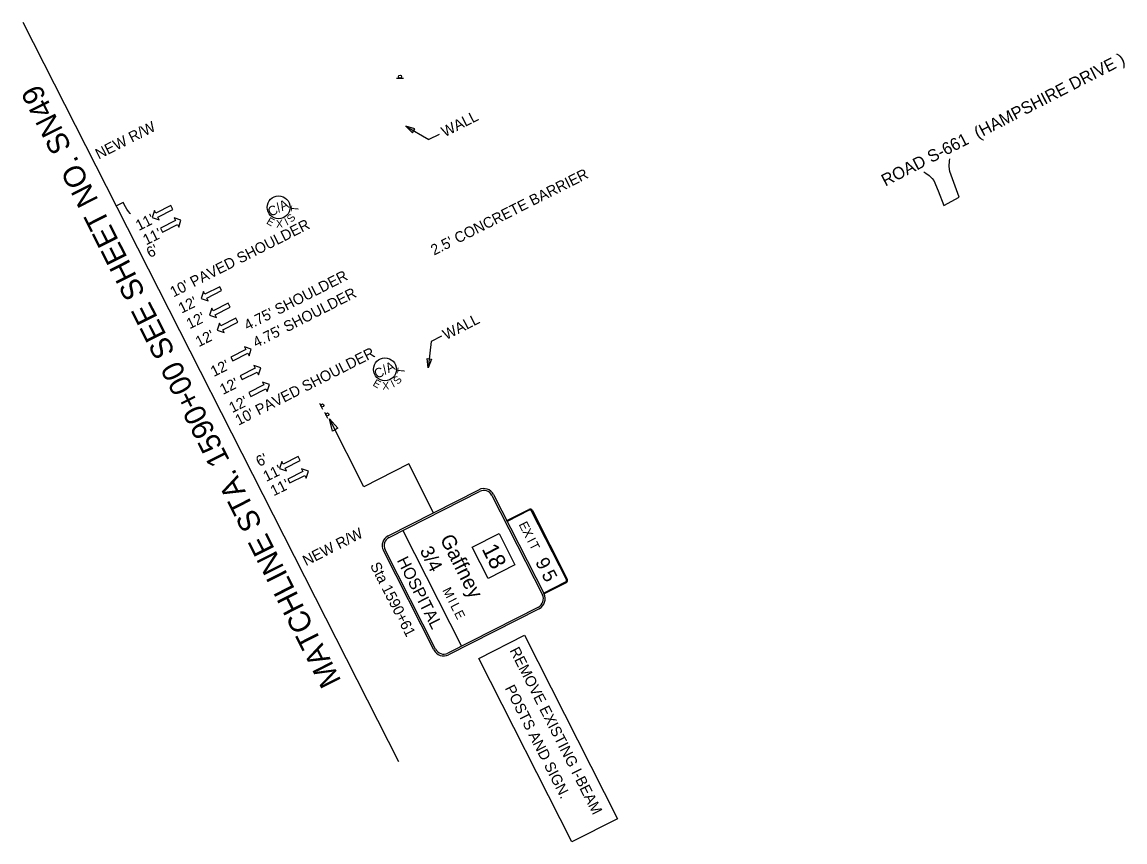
# Model space of a CAD drawing. Extents: x 1806030 to 1807588, y 1188872 to 1190302.
# Drawn here: x 1806030 to 1806754, y 1188872 to 1189411 of the extents above; entities that cross this region are included whole.
import ezdxf

# ---------------------------------------------------------------- set-up
doc = ezdxf.new("R2010")
doc.units = 0
for name, color, linetype in [('RD_EX_Road', 7, 'Continuous'), ('RD_PD_Final_LnLine', 7, 'Continuous'), ('RD_PD_Final_TX', 7, 'Continuous'), ('RD_PD_RW_TX', 7, 'Continuous'), ('RD_SHT_MatchLine', 7, 'Continuous'), ('RD_SHT_TX', 7, 'Continuous'), ('RD_Sketch8', 7, 'Continuous'), ('RD_TX_RoadID', 7, 'Continuous'), ('SN_P_Signs', 7, 'Continuous'), ('TERMINATOR', 7, 'Continuous')]:
    doc.layers.add(name, color=color, linetype=linetype)

# ---------------------------------------------------------------- blocks, each defined once
blk = doc.blocks.new('SARRW2')
at = {"layer": 'RD_PD_Final_LnLine'}
blk.add_lwpolyline([(-12, 1.2), (-12, -1.2), (-2.83, -1.2), (-2.83, -2.83), (0, 0), (-2.83, 2.83), (-2.83, 1.2)], close=True, dxfattribs=at)

msp = doc.modelspace()

# ---------------------------------------------------------------- linework, layer by layer
at = {"layer": 'RD_EX_Road'}
for points in [[(1806621.52, 1189312.18), (1806622.74, 1189311.5), (1806624.98, 1189309.79), (1806626.96, 1189307.79), (1806627.94, 1189306.57), (1806630.79, 1189299.88), (1806634.72, 1189290.21), (1806644.72, 1189295.66), (1806638.64, 1189312.5), (1806638.06, 1189315.79), (1806638.38, 1189319.58), (1806638.6, 1189320.85)], [(1806100.62, 1189284.77), (1806100.52, 1189284.85), (1806099.39, 1189286.28), (1806098.38, 1189287.87), (1806097.49, 1189289.31), (1806095.82, 1189292.25), (1806091.43, 1189289.9)]]:
    msp.add_lwpolyline(points, dxfattribs=at)
at = {"layer": 'RD_PD_Final_TX'}
for p, q in [((1806281.41, 1189342.23), (1806296.64, 1189333.51)), ((1806303.27, 1189336.88), (1806296.64, 1189333.51)), ((1806298.14, 1189200.99), (1806296.2, 1189183.55)), ((1806304.77, 1189204.36), (1806298.14, 1189200.99))]:
    msp.add_line(p, q, dxfattribs=at)
at = {"layer": 'RD_SHT_MatchLine'}
msp.add_line((1806030.12, 1189410.57), (1806276.68, 1188925.24), dxfattribs=at)
at = {"layer": 'RD_Sketch8'}
for centre in [(1806197.9, 1189288.97), (1806267.72, 1189182.63)]:
    msp.add_circle(centre, 7.5, dxfattribs=at)
at = {"layer": 'SN_P_Signs'}
for p, q in [((1806275.38, 1189373.71), (1806279.88, 1189373.71)), ((1806224.75, 1189160.51), (1806226.79, 1189156.49)), ((1806228.04, 1189154.58), (1806230.08, 1189150.57)), ((1806228.04, 1189154.58), (1806230.08, 1189150.57)), ((1806253.9, 1189105.6), (1806231.22, 1189150.23)), ((1806283.32, 1189120.54), (1806253.9, 1189105.6)), ((1806299.6, 1189088.49), (1806283.32, 1189120.54)), ((1806325.07, 1189065.91), (1806342.62, 1189074.83)), ((1806300.89, 1188999.06), (1806267.77, 1189064.24)), ((1806353.07, 1189054.26), (1806335.52, 1189045.34)), ((1806329.34, 1188992.85), (1806359.31, 1189008.07)), ((1806359.31, 1189008.07), (1806420.46, 1188887.7)), ((1806390.49, 1188872.47), (1806329.34, 1188992.85)), ((1806420.46, 1188887.7), (1806390.49, 1188872.47))]:
    msp.add_line(p, q, dxfattribs=at)
msp.add_lwpolyline([(1806233.24, 1189142.03), (1806231.26, 1189150.25), (1806236.88, 1189143.93)], close=True, dxfattribs=at)
for points in [[(1806269.86, 1189073.38), (1806329.34, 1189103.6)], [(1806270.4, 1189072.31), (1806329.89, 1189102.53)], [(1806337.95, 1189099.9), (1806371.07, 1189034.71)], [(1806339.02, 1189100.44), (1806372.14, 1189035.25)], [(1806362.4, 1189090.2), (1806347.95, 1189082.86), (1806347.68, 1189083.4), (1806362.12, 1189090.74)], [(1806386.84, 1189044.74), (1806364.01, 1189089.67)], [(1806364.54, 1189089.95), (1806387.37, 1189045.01)], [(1806279.38, 1189076.87), (1806317.93, 1189000.99)], [(1806342.62, 1189074.83), (1806353.07, 1189054.26)], [(1806299.82, 1188998.51), (1806266.7, 1189063.7)], [(1806335.52, 1189045.34), (1806325.07, 1189065.91)], [(1806371.87, 1189035.79), (1806386.31, 1189043.13)], [(1806386.58, 1189042.59), (1806372.14, 1189035.25), (1806371.87, 1189035.79)], [(1806368.44, 1189026.64), (1806308.95, 1188996.42)], [(1806368.98, 1189025.57), (1806309.5, 1188995.35)]]:
    msp.add_lwpolyline(points, dxfattribs=at)
for centre in [(1806277.64, 1189374.72), (1806226.68, 1189158.95), (1806229.96, 1189153.03), (1806229.96, 1189153.03)]:
    msp.add_circle(centre, 1, dxfattribs=at)
for centre, radius, start, end in [((1806332.61, 1189097.18), 7.2, 26.93166, 116.93166), ((1806332.61, 1189097.18), 6, 26.93166, 116.93166), ((1806362.94, 1189089.13), 1.8, 26.93166, 116.93166), ((1806362.94, 1189089.13), 1.2, 26.93166, 116.93166), ((1806273.12, 1189066.96), 7.2, 116.93166, 206.93166), ((1806273.12, 1189066.96), 6, 116.93166, 206.93166), ((1806385.77, 1189044.2), 1.2, 296.93166, 26.93166), ((1806385.77, 1189044.2), 1.8, 296.93166, 26.93166), ((1806365.72, 1189031.99), 6, 296.93166, 26.93166), ((1806365.72, 1189031.99), 7.2, 296.93166, 26.93166), ((1806306.24, 1189001.77), 7.2, 206.93166, 296.93166), ((1806306.24, 1189001.77), 6, 206.93166, 296.93166)]:
    msp.add_arc(centre, radius, start, end, dxfattribs=at)
at = {"layer": 'TERMINATOR'}
for points in [[(1806287.36, 1189340.55), (1806281.41, 1189342.23), (1806285.87, 1189337.94)], [(1806298.35, 1189189.35), (1806296.2, 1189183.55), (1806295.37, 1189189.68)]]:
    msp.add_lwpolyline(points, close=True, dxfattribs=at)

# ---------------------------------------------------------------- block references
at = {"layer": 'RD_PD_Final_LnLine'}
for p, xscale, yscale, rotation in [((1806114.9, 1189282.3), 1.1999999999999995, 1.2000000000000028, -153.06833411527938), ((1806133.82, 1189280.59), 1.1999999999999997, 1.2000000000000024, 26.931665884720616), ((1806147.04, 1189229.07), 1.1999999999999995, 1.2000000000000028, -153.06833411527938), ((1806152.57, 1189218.18), 1.1999999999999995, 1.2000000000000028, -153.06833411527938), ((1806157.56, 1189208.38), 1.1999999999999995, 1.2000000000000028, -153.06833411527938), ((1806180.01, 1189195.98), 1.1999999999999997, 1.2000000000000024, 26.931665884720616), ((1806186.25, 1189183.7), 1.1999999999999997, 1.2000000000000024, 26.931665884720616), ((1806191.87, 1189172.63), 1.1999999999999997, 1.2000000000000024, 26.931665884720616), ((1806198.59, 1189117.58), 1.1999999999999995, 1.2000000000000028, -153.06833411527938), ((1806217.51, 1189115.86), 1.1999999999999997, 1.2000000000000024, 26.931665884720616)]:
    msp.add_blockref('SARRW2', p, dxfattribs=dict(at, xscale=xscale, yscale=yscale, rotation=rotation))

# ---------------------------------------------------------------- texts
at = {"layer": 'RD_PD_Final_TX'}
for s, rotation, p in [('WALL', 26.93166, (1806306.99, 1189334.91)), ("2.5' CONCRETE BARRIER", 26.6834, (1806299.95, 1189257.28)), ("11'", 26.30484, (1806106.18, 1189273.44)), ("10' PAVED SHOULDER", 26.81776, (1806128.84, 1189229.76)), ("11'", 26.30484, (1806110.98, 1189263.99)), ("6' ", 26.81776, (1806113.37, 1189255.63)), ("4.75' SHOULDER", 26.93166, (1806177.45, 1189207.99)), ("4.75' SHOULDER", 26.93166, (1806183.2, 1189196.66)), ("12'", 26.30484, (1806134.28, 1189219.17)), ("12'", 26.30484, (1806139.51, 1189208.89)), ('WALL', 26.93166, (1806307.87, 1189201.76)), ("12'", 26.30484, (1806145.46, 1189197.16)), ("10' PAVED SHOULDER", 26.81776, (1806171.61, 1189145.62)), ("12'", 26.30484, (1806155.4, 1189177.59)), ("12'", 26.30484, (1806161.39, 1189165.82)), ("12'", 26.30484, (1806167.47, 1189153.85)), ("6' ", 26.81776, (1806185.23, 1189118.54)), ("11'", 26.30484, (1806189.86, 1189108.72)), ("11'", 26.30484, (1806194.66, 1189099.27))]:
    msp.add_text(s, height=7, rotation=rotation, dxfattribs=at).set_placement(p)
at = {"layer": 'RD_PD_RW_TX'}
for rotation, p in [(26.87777, (1806079.82, 1189320.31)), (26.92988, (1806215.93, 1189053.42))]:
    msp.add_text('NEW R/W', height=7, rotation=rotation, dxfattribs=at).set_placement(p)
at = {"layer": 'RD_SHT_TX'}
msp.add_text('MATCHLINE STA. 1590+00 SEE SHEET NO. SN49', height=14.1726, rotation=116.81304, dxfattribs=at).set_placement((1806239.29, 1188978.23))
at = {"layer": 'RD_Sketch8'}
for s, height, rotation, p in [('C/A', 6.25, 26.93166, (1806192.78, 1189282.69)), ('S', 5, 48.72411, (1806206.49, 1189278.67)), ('T', 5, 85.11681, (1806210.93, 1189285.82)), ('E', 5, 330.14291, (1806189.51, 1189278.51)), ('X', 5, 2.57228, (1806196.33, 1189275.63)), ('I', 5, 26.73228, (1806203.32, 1189276.86)), ('C/A', 6.25, 26.93166, (1806262.6, 1189176.35)), ('T', 5, 85.11681, (1806280.75, 1189179.49)), ('E', 5, 330.14291, (1806259.33, 1189172.18)), ('S', 5, 48.72411, (1806276.31, 1189172.33)), ('X', 5, 2.57228, (1806266.15, 1189169.3)), ('I', 5, 26.73228, (1806273.13, 1189170.53))]:
    msp.add_text(s, height=height, rotation=rotation, dxfattribs=at).set_placement(p)
at = {"layer": 'RD_TX_RoadID'}
msp.add_text('ROAD S-661  (HAMPSHIRE DRIVE )', height=8, rotation=27.1461, dxfattribs=at).set_placement((1806596.2, 1189302.52))
at = {"layer": 'SN_P_Signs'}
for s, height, rotation, p in [('E', 6, 296.93166, (1806355.36, 1189080.87)), ('X', 6, 296.93166, (1806357.69, 1189076.27)), ('Gaffney', 9.6, 296.93166, (1806303.62, 1189071.43)), ('18', 10.8, 296.93166, (1806331.06, 1189064.79)), ('I', 6, 296.93166, (1806360.78, 1189070.2)), ('T', 6, 296.93166, (1806362.13, 1189067.54)), ('HOSPITAL', 7.8, 296.93166, (1806275.41, 1189057.32)), ('3/4', 9, 296.93166, (1806290.37, 1189063.74)), ('Sta 1590+61', 7, 296.93175, (1806257.77, 1189053.96)), ('9', 9, 296.93166, (1806366.17, 1189056.28)), ('5', 9, 296.93166, (1806370.29, 1189048.16)), ('M', 6, 296.93166, (1806305.29, 1189037.69)), ('I', 6, 296.93166, (1806308.85, 1189030.67)), ('L', 6, 296.93166, (1806310.48, 1189027.47)), ('E', 6, 296.93166, (1806312.93, 1189022.64)), ('REMOVE EXISTING I-BEAM', 6.9998, 296.93174, (1806349.34, 1188998.2)), ('POSTS AND SIGN.', 6.9998, 296.93174, (1806346.24, 1188973.39))]:
    msp.add_text(s, height=height, rotation=rotation, dxfattribs=at).set_placement(p)

doc.saveas('drawing.dxf')
